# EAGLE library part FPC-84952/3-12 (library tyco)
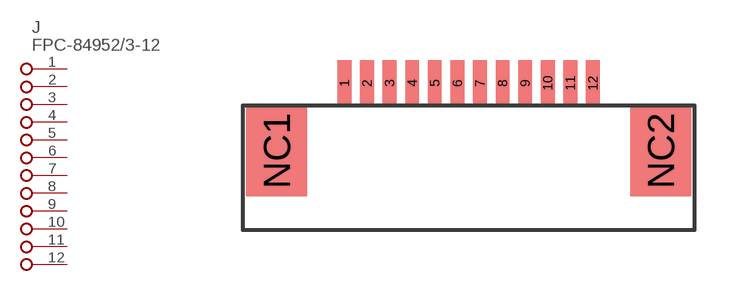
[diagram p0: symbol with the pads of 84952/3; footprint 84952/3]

Designator prefix J

## FPC-84952/3-12  [84952/3]
1  1
2  2
3  3
4  4
5  5
6  6
7  7
8  8
9  9
10  10
11  11
12  12

## Footprint 84952/3 (pad centres in mm)
smd 0.61 x 2: 1 -5.5,1; 2 -4.5,1; 3 -3.5,1; 4 -2.5,1; 5 -1.5,1; 6 -0.5,1; 7 0.5,1; 8 1.5,1; 9 2.5,1; 10 3.5,1; 11 4.5,1; 12 5.5,1
smd 2.7 x 4: NC1 -8.5,-2; NC2 8.5,-2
